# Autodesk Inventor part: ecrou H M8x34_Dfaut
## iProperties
Created: 2006-03
Part Number: ecrou H M8x34_Dfaut
Document SubType Name: Modeling
Designer: Flavien MARTY
Author: Flavien MARTY
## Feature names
1. Base1
